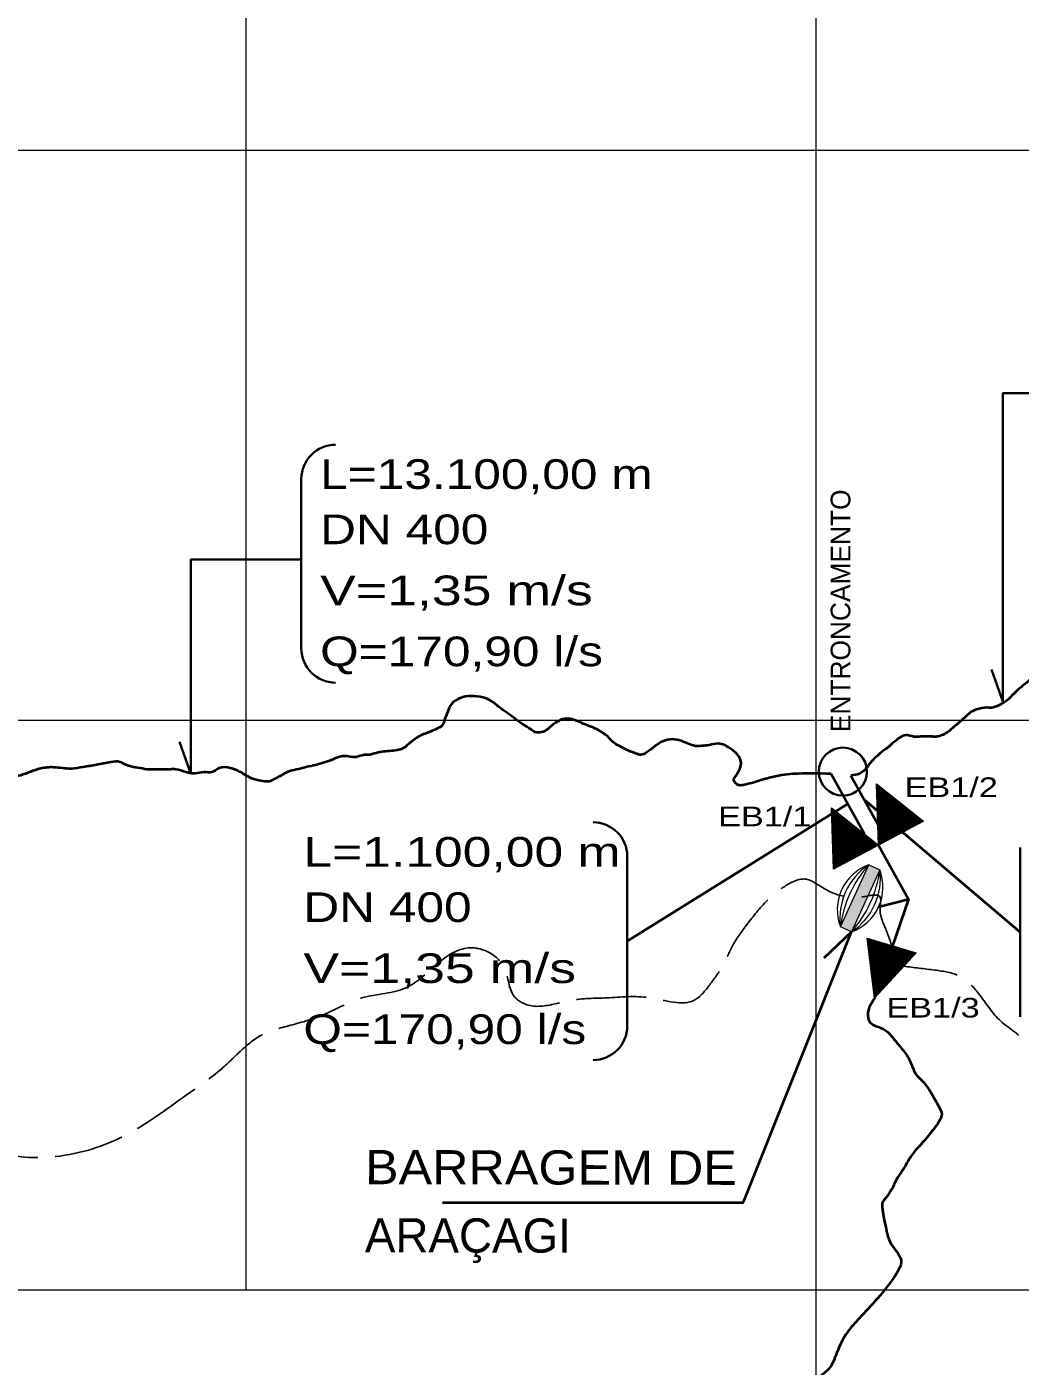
# Model space of a CAD drawing. Extents: x 0 to 1772, y 0 to 1188.
# Drawn here: x 781.9 to 892.9, y 181.7 to 331.4 of the extents above; entities that cross this region are included whole.
import ezdxf
from ezdxf.enums import TextEntityAlignment as Align

# ---------------------------------------------------------------- set-up
doc = ezdxf.new("R2010")
doc.units = 0
doc.header["$LTSCALE"] = 1.3
doc.linetypes.add('DOT_DASHED', pattern=[7.7, 5, -1.2, 0.3, -1.2])
doc.linetypes.add('LONG_DASHED', pattern=[7.5, 6, -1.5])
for name, color, linetype, lineweight in [('1', 7, 'DOT_DASHED', 13), ('4', 7, 'Continuous', 13), ('5', 7, 'LONG_DASHED', 25), ('6', 7, 'Continuous', 40), ('63', 7, 'Continuous', 25), ('8', 7, 'Continuous', 35)]:
    doc.layers.add(name, color=color, linetype=linetype, lineweight=lineweight)

msp = doc.modelspace()

# ---------------------------------------------------------------- hatches: boundary and pattern name
at = {"layer": '1'}
msp.add_hatch(color=256, dxfattribs=at).paths.add_polyline_path([(875.969, 237.731), (877.196, 237.169), (874.015, 230.221), (872.787, 230.783)])

# ---------------------------------------------------------------- linework, layer by layer
at = {"layer": '1', "linetype": 'Continuous'}
msp.add_lwpolyline([(875.969, 237.731), (877.196, 237.169), (874.015, 230.221), (872.787, 230.783)], close=True, dxfattribs=at)
for centre, radius, start, end in [((877.811, 232.684), 5.372, 110.05739, 200.73161), ((879.884, 231.735), 7.161, 123.14568, 187.64331), ((885.586, 229.124), 12.906, 138.17313, 172.61588), ((872.172, 235.267), 5.372, 290.05739, 20.73161), ((870.099, 236.216), 7.161, 303.14569, 7.64332), ((864.398, 238.827), 12.906, 318.17313, 352.61587)]:
    msp.add_arc(centre, radius, start, end, dxfattribs=at)
at = {"layer": '4'}
for p, q in [((876.812, 246.753), (876.818, 246.775)), ((876.82, 246.513), (876.886, 246.722)), ((876.829, 246.272), (876.953, 246.668)), ((876.838, 246.031), (877.02, 246.615)), ((876.846, 245.791), (877.087, 246.562)), ((876.855, 245.55), (877.154, 246.508)), ((876.864, 245.309), (877.221, 246.455)), ((876.873, 245.069), (877.289, 246.402)), ((876.881, 244.828), (877.356, 246.349)), ((876.89, 244.587), (877.423, 246.295)), ((876.899, 244.347), (877.49, 246.242)), ((876.907, 244.106), (877.557, 246.189)), ((876.916, 243.865), (877.625, 246.135)), ((876.925, 243.625), (877.692, 246.082)), ((876.933, 243.384), (877.759, 246.029)), ((876.942, 243.143), (877.826, 245.976)), ((876.951, 242.903), (877.893, 245.922)), ((876.959, 242.662), (877.96, 245.869)), ((876.968, 242.422), (878.028, 245.816)), ((876.977, 242.181), (878.095, 245.763)), ((876.985, 241.94), (878.162, 245.709)), ((876.994, 241.7), (878.229, 245.656)), ((877.003, 241.459), (878.296, 245.603)), ((877.012, 241.218), (878.363, 245.549)), ((877.02, 240.978), (878.431, 245.496)), ((877.029, 240.737), (878.498, 245.443)), ((877.038, 240.496), (878.565, 245.39)), ((877.046, 240.256), (878.632, 245.336)), ((877.055, 240.015), (878.699, 245.283)), ((877.12, 239.955), (878.767, 245.23)), ((877.221, 240.009), (878.834, 245.176)), ((877.321, 240.062), (878.901, 245.123)), ((877.421, 240.115), (878.968, 245.07)), ((877.522, 240.169), (879.035, 245.017)), ((877.622, 240.222), (879.102, 244.963)), ((877.723, 240.275), (879.17, 244.91)), ((877.823, 240.329), (879.237, 244.857)), ((877.924, 240.382), (879.304, 244.803)), ((878.024, 240.435), (879.371, 244.75)), ((878.125, 240.489), (879.438, 244.697)), ((878.225, 240.542), (879.505, 244.644)), ((878.326, 240.595), (879.573, 244.59)), ((878.426, 240.649), (879.64, 244.537)), ((878.527, 240.702), (879.707, 244.484)), ((878.627, 240.755), (879.774, 244.43)), ((878.727, 240.809), (879.841, 244.377)), ((878.828, 240.862), (879.909, 244.324)), ((878.928, 240.915), (879.976, 244.271)), ((879.029, 240.969), (880.043, 244.217)), ((879.129, 241.022), (880.11, 244.164)), ((871.78, 244.082), (871.787, 244.103)), ((871.789, 243.841), (871.854, 244.05)), ((871.798, 243.6), (871.922, 243.997)), ((871.807, 243.36), (871.989, 243.943)), ((871.815, 243.119), (872.056, 243.89)), ((871.824, 242.878), (872.123, 243.837)), ((871.833, 242.638), (872.19, 243.783)), ((871.841, 242.397), (872.257, 243.73)), ((871.85, 242.156), (872.325, 243.677)), ((871.859, 241.916), (872.392, 243.624)), ((871.867, 241.675), (872.459, 243.57)), ((871.876, 241.434), (872.526, 243.517)), ((871.885, 241.194), (872.593, 243.464)), ((871.893, 240.953), (872.66, 243.411)), ((871.902, 240.712), (872.728, 243.357)), ((871.911, 240.472), (872.795, 243.304)), ((871.919, 240.231), (872.862, 243.251)), ((871.928, 239.99), (872.929, 243.197)), ((871.937, 239.75), (872.996, 243.144)), ((871.946, 239.509), (873.064, 243.091)), ((871.954, 239.269), (873.131, 243.038)), ((871.963, 239.028), (873.198, 242.984)), ((871.972, 238.787), (873.265, 242.931)), ((871.98, 238.547), (873.332, 242.878)), ((871.989, 238.306), (873.399, 242.824)), ((871.998, 238.065), (873.467, 242.771)), ((872.006, 237.825), (873.534, 242.718)), ((872.015, 237.584), (873.601, 242.665)), ((879.23, 241.075), (880.177, 244.111)), ((879.33, 241.129), (880.244, 244.058)), ((879.431, 241.182), (880.312, 244.004)), ((879.531, 241.235), (880.379, 243.951)), ((879.632, 241.289), (880.446, 243.898)), ((879.732, 241.342), (880.513, 243.844)), ((879.832, 241.396), (880.58, 243.791)), ((879.933, 241.449), (880.647, 243.738)), ((880.033, 241.502), (880.715, 243.685)), ((880.134, 241.556), (880.782, 243.631)), ((880.234, 241.609), (880.849, 243.578)), ((880.335, 241.662), (880.916, 243.525)), ((880.435, 241.716), (880.983, 243.471)), ((880.536, 241.769), (881.05, 243.418)), ((880.636, 241.822), (881.118, 243.365)), ((880.737, 241.876), (881.185, 243.312)), ((880.837, 241.929), (881.252, 243.258)), ((880.938, 241.982), (881.319, 243.205)), ((881.038, 242.036), (881.386, 243.152)), ((881.138, 242.089), (881.454, 243.098)), ((881.239, 242.142), (881.521, 243.045)), ((881.339, 242.196), (881.588, 242.992)), ((881.44, 242.249), (881.655, 242.939)), ((881.54, 242.302), (881.722, 242.885)), ((881.641, 242.356), (881.789, 242.832)), ((881.741, 242.409), (881.857, 242.779)), ((881.842, 242.462), (881.924, 242.726)), ((881.942, 242.516), (881.991, 242.672)), ((872.024, 237.343), (873.668, 242.611)), ((872.089, 237.284), (873.735, 242.558)), ((872.189, 237.337), (873.802, 242.505)), ((872.29, 237.39), (873.87, 242.451)), ((872.39, 237.444), (873.937, 242.398)), ((872.491, 237.497), (874.004, 242.345)), ((872.591, 237.55), (874.071, 242.292)), ((872.692, 237.604), (874.138, 242.238)), ((872.792, 237.657), (874.206, 242.185)), ((872.893, 237.71), (874.273, 242.132)), ((872.993, 237.764), (874.34, 242.079)), ((873.093, 237.817), (874.407, 242.025)), ((873.194, 237.87), (874.474, 241.972)), ((873.294, 237.924), (874.541, 241.919)), ((873.395, 237.977), (874.609, 241.865)), ((873.495, 238.03), (874.676, 241.812)), ((873.596, 238.084), (874.743, 241.759)), ((873.696, 238.137), (874.81, 241.706)), ((873.797, 238.19), (874.877, 241.652)), ((873.897, 238.244), (874.944, 241.599)), ((873.998, 238.297), (875.012, 241.546)), ((874.098, 238.35), (875.079, 241.492)), ((874.199, 238.404), (875.146, 241.439)), ((874.299, 238.457), (875.213, 241.386)), ((874.399, 238.51), (875.28, 241.333)), ((874.5, 238.564), (875.347, 241.279)), ((874.6, 238.617), (875.415, 241.226)), ((874.701, 238.67), (875.482, 241.173)), ((882.043, 242.569), (882.058, 242.619)), ((874.801, 238.724), (875.549, 241.119)), ((874.902, 238.777), (875.616, 241.066)), ((875.002, 238.831), (875.683, 241.013)), ((875.103, 238.884), (875.751, 240.96)), ((875.203, 238.937), (875.818, 240.906)), ((875.304, 238.991), (875.885, 240.853)), ((875.404, 239.044), (875.952, 240.8)), ((875.504, 239.097), (876.019, 240.746)), ((875.605, 239.151), (876.086, 240.693)), ((875.705, 239.204), (876.154, 240.64)), ((875.806, 239.257), (876.221, 240.587)), ((875.906, 239.311), (876.288, 240.533)), ((876.007, 239.364), (876.355, 240.48)), ((876.107, 239.417), (876.422, 240.427)), ((876.208, 239.471), (876.489, 240.374)), ((876.308, 239.524), (876.557, 240.32)), ((876.409, 239.577), (876.624, 240.267)), ((876.509, 239.631), (876.691, 240.214)), ((876.609, 239.684), (876.758, 240.16)), ((876.71, 239.737), (876.825, 240.107)), ((876.81, 239.791), (876.893, 240.054)), ((876.911, 239.844), (876.96, 240.001)), ((877.011, 239.897), (877.027, 239.947)), ((875.801, 229.449), (875.943, 229.465)), ((875.811, 229.369), (876.137, 229.407)), ((875.82, 229.29), (876.331, 229.349)), ((875.83, 229.21), (876.524, 229.291)), ((875.84, 229.131), (876.718, 229.233)), ((875.849, 229.052), (876.912, 229.175)), ((875.859, 228.972), (877.106, 229.117)), ((875.869, 228.893), (877.3, 229.059)), ((875.878, 228.813), (877.494, 229.001)), ((875.888, 228.734), (877.688, 228.943)), ((875.898, 228.655), (877.881, 228.885)), ((875.908, 228.575), (878.075, 228.827)), ((875.917, 228.496), (878.269, 228.769)), ((875.927, 228.416), (878.463, 228.711)), ((875.937, 228.337), (878.657, 228.653)), ((875.946, 228.258), (878.851, 228.595)), ((875.956, 228.178), (879.044, 228.537)), ((875.966, 228.099), (879.238, 228.479)), ((875.975, 228.019), (879.432, 228.421)), ((875.985, 227.94), (879.626, 228.363)), ((875.995, 227.86), (879.82, 228.305)), ((876.004, 227.781), (880.014, 228.247)), ((876.014, 227.702), (880.207, 228.189)), ((876.024, 227.622), (880.401, 228.131)), ((876.033, 227.543), (880.595, 228.073)), ((876.043, 227.463), (880.789, 228.015)), ((876.053, 227.384), (880.983, 227.957)), ((876.062, 227.305), (881.177, 227.899)), ((876.072, 227.225), (881.2, 227.821)), ((876.082, 227.146), (881.117, 227.731)), ((876.091, 227.066), (881.034, 227.641)), ((876.101, 226.987), (880.952, 227.551)), ((876.111, 226.907), (880.869, 227.461)), ((876.12, 226.828), (880.786, 227.37)), ((876.13, 226.749), (880.703, 227.28)), ((876.14, 226.669), (880.62, 227.19)), ((876.15, 226.59), (880.538, 227.1)), ((876.159, 226.51), (880.455, 227.01)), ((876.169, 226.431), (880.372, 226.92)), ((876.179, 226.352), (880.289, 226.829)), ((876.188, 226.272), (880.206, 226.739)), ((876.198, 226.193), (880.124, 226.649)), ((876.208, 226.113), (880.041, 226.559)), ((876.217, 226.034), (879.958, 226.469)), ((876.227, 225.955), (879.875, 226.379)), ((876.237, 225.875), (879.792, 226.288)), ((876.246, 225.796), (879.71, 226.198)), ((876.256, 225.716), (879.627, 226.108)), ((876.266, 225.637), (879.544, 226.018)), ((876.275, 225.557), (879.461, 225.928)), ((876.285, 225.478), (879.378, 225.838)), ((876.295, 225.399), (879.296, 225.747)), ((876.304, 225.319), (879.213, 225.657)), ((876.314, 225.24), (879.13, 225.567)), ((876.324, 225.16), (879.047, 225.477)), ((876.333, 225.081), (878.964, 225.387)), ((876.343, 225.002), (878.882, 225.297)), ((876.353, 224.922), (878.799, 225.206)), ((876.363, 224.843), (878.716, 225.116)), ((876.372, 224.763), (878.633, 225.026)), ((876.382, 224.684), (878.55, 224.936)), ((876.392, 224.605), (878.468, 224.846)), ((876.401, 224.525), (878.385, 224.756)), ((876.411, 224.446), (878.302, 224.665)), ((876.421, 224.366), (878.219, 224.575)), ((876.43, 224.287), (878.136, 224.485)), ((876.44, 224.207), (878.054, 224.395)), ((876.45, 224.128), (877.971, 224.305)), ((876.459, 224.049), (877.888, 224.215)), ((876.469, 223.969), (877.805, 224.125)), ((876.479, 223.89), (877.722, 224.034)), ((876.488, 223.81), (877.64, 223.944)), ((876.498, 223.731), (877.557, 223.854)), ((876.508, 223.652), (877.474, 223.764)), ((876.517, 223.572), (877.391, 223.674)), ((876.527, 223.493), (877.308, 223.584)), ((876.537, 223.413), (877.226, 223.493)), ((876.546, 223.334), (877.143, 223.403)), ((876.556, 223.254), (877.06, 223.313)), ((876.566, 223.175), (876.977, 223.223)), ((876.575, 223.096), (876.894, 223.133)), ((876.585, 223.016), (876.812, 223.043)), ((876.595, 222.937), (876.729, 222.952)), ((876.605, 222.857), (876.646, 222.862))]:
    msp.add_line(p, q, dxfattribs=at)
for points in [[(877.058, 239.922), (876.811, 246.781), (882.09, 242.594)], [(872.027, 237.251), (871.78, 244.109), (877.058, 239.922)], [(881.251, 227.877), (876.609, 222.822), (875.794, 229.51)]]:
    msp.add_lwpolyline(points, close=True, dxfattribs=at)
at = {"layer": '4', "lineweight": 35}
msp.add_ellipse((873.061, 248.142), major_axis=(2.687, 0), ratio=0.998913, dxfattribs=at)
at = {"layer": '5'}
for points in [[(878.537, 228.689), (877.747, 230.803), (877.216, 232.856), (877.212, 234.145), (875.304, 234.14), (873.443, 234.134), (870.863, 235.13), (868.856, 236.127), (866.699, 235.399), (864.745, 233.881), (862.487, 231.228), (860.772, 228.743), (859.528, 226.282), (858.189, 224.317), (856.519, 222.611), (851.453, 222.861), (846.687, 222.847), (842.65, 222.567), (841.119, 222.222), (837.914, 222.032), (836.297, 223.062), (835.291, 226.072), (833.291, 228.044), (831.386, 228.438), (828.195, 227.04), (824.327, 224.014), (819.287, 222.831), (815.491, 221.162), (811.543, 219.831), (808.084, 218.691), (805.568, 216.724), (803.353, 214.682), (799.83, 212.067), (792.437, 207.269), (784.559, 205.048), (778.069, 205.977), (773.613, 210.91), (772.858, 212.956), (769.159, 215.193), (767.459, 216.387), (765.657, 218.341), (765.141, 219.205), (765.137, 220.503), (764.513, 221.529), (763.51, 222.554), (762.293, 222.956), (761.377, 222.061), (760.33, 219.921), (759.364, 217.782), (758.883, 215.941), (756.997, 214.123), (755.138, 212.495), (754.521, 211.006), (752.137, 208.282), (749.213, 206.239), (747.084, 206.895), (747.074, 210.443), (746.498, 213.422), (745.215, 215.548), (743.038, 216.629), (742.088, 218.424), (740.996, 219.84)], [(987.842, 230.305), (985.628, 226.476), (982.964, 222.096), (976.206, 220.383), (964.658, 218.233), (961.115, 225.134), (959.277, 227.385), (956.197, 220.747), (950.998, 215.794), (940.713, 215.764), (940.699, 220.277), (940.263, 220.276), (938.015, 222.808), (938.024, 219.564), (934.079, 219.552), (928.422, 226.588), (925.891, 224.888), (927.742, 218.264), (927.76, 212.34), (922.124, 212.323), (915.354, 214.56), (900.56, 214.516), (895.639, 215.427), (893.532, 217.905), (890.518, 220.428), (888.219, 223.335), (886.162, 225.239), (883.344, 225.947), (879.87, 226.373)]]:
    msp.add_spline(points, degree=3, dxfattribs=at)
at = {"layer": '6'}
for p, q in [((871.753, 247.891), (875.471, 241.181)), ((873.969, 247.703), (876.973, 242.282)), ((877.058, 239.922), (880.4, 233.893))]:
    msp.add_line(p, q, dxfattribs=at)
msp.add_lwpolyline([(877.056, 233.03), (880.4, 233.893), (878.618, 228.665)], dxfattribs=at)
for points in [[(900.011, 261.624), (898.769, 261.87), (898.141, 261.868), (897.279, 261.314), (896.18, 260.401), (895.236, 259.564), (894.548, 258.927), (893.539, 258.04), (892.746, 257.394), (891.965, 256.646), (891.359, 256.07), (890.879, 255.764), (890.301, 255.473), (889.863, 255.301), (889.199, 255.299), (887.983, 255.082), (887.246, 254.698), (886.65, 254.16), (885.617, 253.269), (884.707, 252.513), (884.098, 252.205), (883.587, 252.056), (883.052, 252.054), (882.455, 252.053), (881.771, 252.051), (881.003, 252.048), (880.111, 252.217), (879.304, 251.865), (878.186, 250.911)], [(871.753, 247.891), (867.489, 247.881), (866.216, 247.741), (864.81, 247.439), (863.362, 247.013), (862.381, 246.733), (861.769, 246.617), (861.48, 246.616), (861.192, 246.763), (860.985, 246.954), (860.901, 247.089), (860.86, 247.206), (860.905, 247.37), (861.166, 247.743), (861.421, 248.181), (861.63, 248.68), (861.628, 249.461), (861.249, 250.089), (860.785, 250.501), (860.352, 250.813), (859.859, 251.093), (859.103, 251.268), (858.121, 251.11), (857.317, 251.008), (856.575, 251.005), (856.178, 251.11), (855.445, 251.403), (854.985, 251.571), (853.985, 251.763), (852.993, 251.539), (852.02, 250.967), (851.163, 250.3), (850.47, 250.019), (849.942, 250.173), (848.898, 250.578), (848.052, 251.015), (847.377, 251.429), (846.982, 251.863), (846.327, 252.41), (845.549, 252.874), (844.722, 253.229), (844.021, 253.503), (843.304, 253.829), (842.577, 254.027), (841.767, 254.024), (841.21, 253.743), (840.692, 253.422), (840.136, 252.945), (839.753, 252.679), (839.386, 252.555), (838.671, 252.553), (838.173, 252.879), (837.391, 253.367), (836.361, 254.103), (835.536, 254.698), (834.667, 255.364), (833.722, 256.072), (832.869, 256.414), (831.515, 256.597), (830.303, 256.361), (829.308, 255.701), (828.904, 254.847), (828.534, 253.898), (828.332, 253.375), (828.216, 253.238), (827.752, 252.962), (826.949, 252.601), (825.764, 252.122), (825.064, 251.658), (824.382, 251.111), (823.857, 250.711), (823.449, 250.581), (821.759, 250.383), (820.917, 250.221), (820.022, 250.005), (819.577, 250.004), (818.672, 249.769), (817.329, 249.881), (816.044, 249.499), (814.143, 248.872), (813.096, 248.641), (811.965, 248.367), (811.015, 248.108), (810.477, 247.81)], [(878.2, 250.935), (876.915, 249.925), (876.235, 249.24), (875.802, 248.69), (875.372, 248.209), (874.922, 247.903), (873.969, 247.703)], [(810.477, 247.81), (809.84, 247.46), (809.386, 247.225), (808.978, 247.05), (808.438, 247.048), (807.594, 247.192), (806.798, 247.472), (806.374, 247.698), (805.659, 248.129), (804.633, 248.527), (803.328, 248.523), (802.525, 248.08), (801.635, 248.078), (800.638, 247.949), (799.642, 248.075), (798.524, 248.394), (797.915, 248.392), (796.704, 248.388), (795.318, 248.384), (794.258, 248.579), (793.233, 248.775), (792.845, 248.956), (792.282, 249.217), (791.253, 249.214), (789.639, 248.883), (788.152, 248.652), (786.834, 248.471), (784.889, 248.621), (783.377, 248.478), (781.147, 247.722), (780.179, 247.501), (778.702, 247.222), (777.052, 246.584), (776.405, 246.395), (775.484, 246.519), (774.335, 246.824), (773.451, 247.357), (772.185, 247.813), (771.049, 248.239), (769.981, 248.592), (768.996, 248.832), (768.419, 249.061)], [(876.637, 222.852), (875.879, 220.627), (876.25, 219.965), (877.145, 219.552), (877.678, 219.294), (879.095, 217.833), (879.992, 216.745), (880.709, 215.45), (881.231, 214.31), (881.985, 213.508), (882.857, 212.329), (883.743, 210.775), (884.108, 209.829), (883.839, 209.05), (883.18, 208.14), (882.78, 207.632), (882.201, 206.907), (881.427, 206.068), (880.572, 204.971), (879.881, 203.804), (879.179, 202.742), (878.641, 201.657), (878.021, 200.666), (877.459, 199.852), (877.46, 199.44), (877.616, 198.417), (877.771, 197.652), (878.474, 195.316), (879.593, 193.258), (879.123, 192.143), (876.934, 189.239), (874.881, 187.004), (873.578, 185.469), (872.361, 183.097), (871.448, 181.312), (870.477, 180.362), (870.147, 179.079), (869.32, 176.514), (867.906, 174.866), (866.744, 173.505), (865.68, 172.701), (864.328, 172.286), (863.879, 171.443), (863.534, 170.128), (863.333, 168.711), (863.337, 167.364), (862.912, 165.63), (862.65, 164.11), (862.655, 162.489), (862.659, 161.141), (862.663, 159.793), (863.239, 159.164), (863.467, 158.18), (863.47, 157.276), (863.154, 156.291), (862.679, 155.135), (862.398, 153.523), (861.935, 152.014), (861.618, 151.053), (861.414, 150.458), (861.69, 149.831), (862.321, 148.667), (862.322, 148.461), (862.917, 147.857), (863.318, 147.242), (863.857, 146.603), (864.308, 145.961), (864.831, 145.131), (865.23, 144.326), (865.442, 144.004), (866.185, 144.18), (866.68, 144.553), (867.571, 144.978), (868.376, 145.477), (869.142, 146.075), (869.884, 146.76), (870.738, 147.184), (871.11, 147.185), (871.757, 147.571), (873.27, 148.065), (874.608, 148.337), (875.9, 148.807), (876.656, 148.985), (877.507, 148.719), (878.311, 148.5)]]:
    msp.add_spline(points, degree=3, dxfattribs=at)
at = {"layer": '63', "lineweight": 13}
for p, q in [((806.383, 190.159), (806.383, 419.523)), ((870.095, 62.735), (870.095, 419.523)), ((1175.913, 317.583), (487.822, 317.583)), ((1175.913, 253.871), (487.822, 253.871)), ((1175.913, 190.159), (487.822, 190.159))]:
    msp.add_line(p, q, dxfattribs=at)
at = {"layer": '8'}
for p, q in [((812.538, 261.91), (812.538, 280.866)), ((848.96, 229.184), (873.612, 244.536)), ((892.882, 220.706), (892.882, 239.662)), ((848.96, 219.706), (848.96, 238.662))]:
    msp.add_line(p, q, dxfattribs=at)
at = {"layer": '8', "lineweight": 40}
for p, q in [((875.471, 244.992), (892.882, 230.184)), ((828.303, 199.962), (861.91, 199.962))]:
    msp.add_line(p, q, dxfattribs=at)
at = {"layer": '8'}
for points in [[(903.308, 290.466), (890.959, 290.466), (890.959, 255.994), (889.692, 259.561)], [(812.538, 271.867), (800.189, 271.867), (800.189, 247.906), (798.922, 251.472)]]:
    msp.add_lwpolyline(points, dxfattribs=at)
at = {"layer": '8', "lineweight": 40}
msp.add_lwpolyline([(861.947, 199.987), (874.015, 230.221), (870.928, 227.295)], dxfattribs=at)
at = {"layer": '8'}
for centre, start, end in [((816.361, 280.866), 90, 180), ((816.361, 280.866), 90, 180), ((816.361, 280.866), 90, 180), ((816.361, 261.91), 180, 270), ((845.137, 238.662), 0, 90), ((845.137, 238.662), 0, 90), ((845.137, 238.662), 0, 90), ((845.137, 219.706), 270, 0)]:
    msp.add_arc(centre, 3.823, start, end, dxfattribs=at)
at = {"layer": '8', "lineweight": 40}
msp.add_arc((861.91, 200.002), 0.04, 270, 338.24127, dxfattribs=at)

# ---------------------------------------------------------------- texts
at = {"layer": '4'}
msp.add_text('ENTRONCAMENTO', height=2.2, rotation=90.006, dxfattribs=at).set_placement((873.903, 266.125), align=Align.CENTER)
at = {"layer": '5', "width": 1.3}
for s, p in [('EB1/2', (885.175, 245.296)), ('EB1/1', (864.334, 242.027)), ('EB1/3', (883.143, 220.643))]:
    msp.add_text(s, height=2.2, rotation=0.006, dxfattribs=at).set_placement(p, align=Align.CENTER)
at = {"layer": '8'}
for s, width, p in [('L=13.100,00 m', 1.25, (814.636, 279.753)), ('DN 400', 1.25, (814.636, 273.573)), ('V=1,35 m/s', 1.35, (814.636, 266.75)), ('Q=170,90 l/s', 1.25, (814.636, 259.926)), ('L=1.100,00 m', 1.3, (812.764, 237.507)), ('DN 400', 1.25, (812.764, 231.327)), ('V=1,35 m/s', 1.35, (812.764, 224.504)), ('Q=170,90 l/s', 1.25, (812.764, 217.68))]:
    msp.add_text(s, height=3.319, dxfattribs=dict(at, width=width)).set_placement(p)
at = {"layer": '8', "width": 1.1}
msp.add_text('BARRAGEM DE ', height=3.823, rotation=359.896, dxfattribs=at).set_placement((819.657, 202.01))
at = {"layer": '8'}
msp.add_text('ARAÇAGI', height=3.823, rotation=359.896, dxfattribs=at).set_placement((819.643, 194.387))

doc.saveas('drawing.dxf')
